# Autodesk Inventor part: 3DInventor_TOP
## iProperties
Created: 2006-11
Part Number: 3DInventor_TOP
Document SubType Name: Modeling
Designer: conardl1
Density: 1 g/cm^3
DESCRIPTION: Top Part (for arrow control)
MODELED_BY: L Conard
Author: conardl1
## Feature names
1. Base1
